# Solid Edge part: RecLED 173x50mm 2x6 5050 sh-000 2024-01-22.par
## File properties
Author: jaroslaw.przewlocki
Template: iso metric part.par
Last saved by: jaroslaw.przewlocki
Revision: 2
Application: Solid Edge
Gęstość: 0,000 kg/m^3
Dokładność: 0,990
Username: jaroslaw.przewlocki
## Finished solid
Body 1: solid body, 990 faces, 2509 edges, 1584 vertices.
  Faces by surface: plane 467, cylinder 260, torus 104, cone 88, spline 50, sphere 20, swept 1
  Edges by curve: line 1264, curve on surface 677, circle 276, spline 160, ellipse 132
Bounding box of the edges (mm; curved faces can reach further): 49.500 x 4.950 x 172.200, from (-24.75, -3.45, -86.1) to (24.75, 1.5, 86.1).
Cylindrical faces by radius (mm): R0.199 x2, R0.2 x78, R0.2002 x4, R0.2169 x6, R0.25 x24, R0.3 x4, R0.3373 x6, R0.4 x16, R0.4006 x4, R0.4008 x4, R0.525 x4, R0.6 x24, R1 x14, R1.05 x12, R1.0894 x4, R1.0991 x8, R1.1 x28, R1.5342 x3, R1.5343 x1, R1.7456 x1, R1.75 x3, R3.7549 x1, R5.3685 x1, R5.3987 x1, R5.4728 x1, R5.8982 x1, R7.5931 x1, R7.8648 x1, R8.5931 x1, R10.3711 x1, R11.964 x1
Conical faces (half-angle, radius in mm at the cone's reference point): 0.3913 deg R1.0968 x4, 0.447 deg R1.0952 x4, 0.464 deg R1.0955 x4, 0.5 deg R0.5056 x8, 0.5 deg R1.0082 x8, 1 deg R0.5511 x4, 10 deg R0.2132 x4, 10 deg R0.4132 x4, 15.6748 deg R1.1041 x2, 15.6751 deg R1.1041 x2, 15.7937 deg R1.1267 x2, 15.7938 deg R1.1267 x2, 18.4844 deg R1.0657 x8, 18.9316 deg R0.5099 x4, 19.4337 deg R0.5111 x4, 27.363 deg R0.6214 x4, 40.1968 deg R0.519 x2, 40.228 deg R0.5176 x2, 42.9179 deg R0.4919 x2, 42.9331 deg R0.4916 x2, 45 deg R0.575 x4, 45 deg R0.625 x8
Toroidal faces (ring radius, tube radius in mm): R0.0958 r0.3997 x8, R0.1 r0.2 x2, R0.1075 r0.4 x4, R0.1101 r0.4001 x4, R0.1216 r0.4 x4, R0.1234 r0.4 x4, R0.1634 r0.2287 x2, R0.1641 r0.2287 x2, R0.3286 r0.2001 x2, R0.3702 r0.4 x4, R0.3818 r0.2 x4, R0.4163 r0.3984 x4, R0.4824 r0.2001 x2, R0.4952 r0.2 x2, R0.6008 r0.3968 x4, R0.6009 r0.3969 x4, R0.6227 r0.2 x2, R0.6235 r0.2 x2, R0.8 r0.2 x8, R0.8522 r0.3 x4, R0.9002 r0.2 x2, R0.9018 r0.2 x2, R0.9181 r0.2227 x4, R0.9197 r0.223 x2, R0.9199 r0.223 x2, R0.9663 r0.2263 x2, R0.9665 r0.2263 x2, R1.3 r0.2 x4, R1.327 r1.1 x4, R1.3271 r1.1 x4, R1.8741 r0.2175 x2, R1.8987 r0.2 x2
Spherical faces by radius (mm): R0.2 x16, R0.6 x4
Planar faces by outward normal: +x 45, +y 15, +z 41, -x 45, -y 73, -z 60, oblique 188
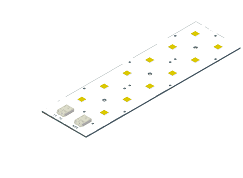
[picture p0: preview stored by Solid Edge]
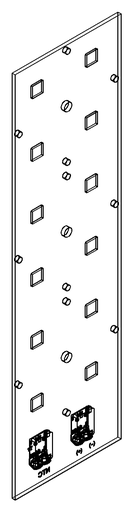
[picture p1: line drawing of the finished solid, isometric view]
